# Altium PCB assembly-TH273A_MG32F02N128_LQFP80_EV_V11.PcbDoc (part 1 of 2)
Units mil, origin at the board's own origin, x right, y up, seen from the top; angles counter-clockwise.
Board outline 4724.41 x 2637.8 mil, 2 copper layers (Top Layer, Bottom Layer); 182 components, 166 nets, 741 pads, 331 vias.
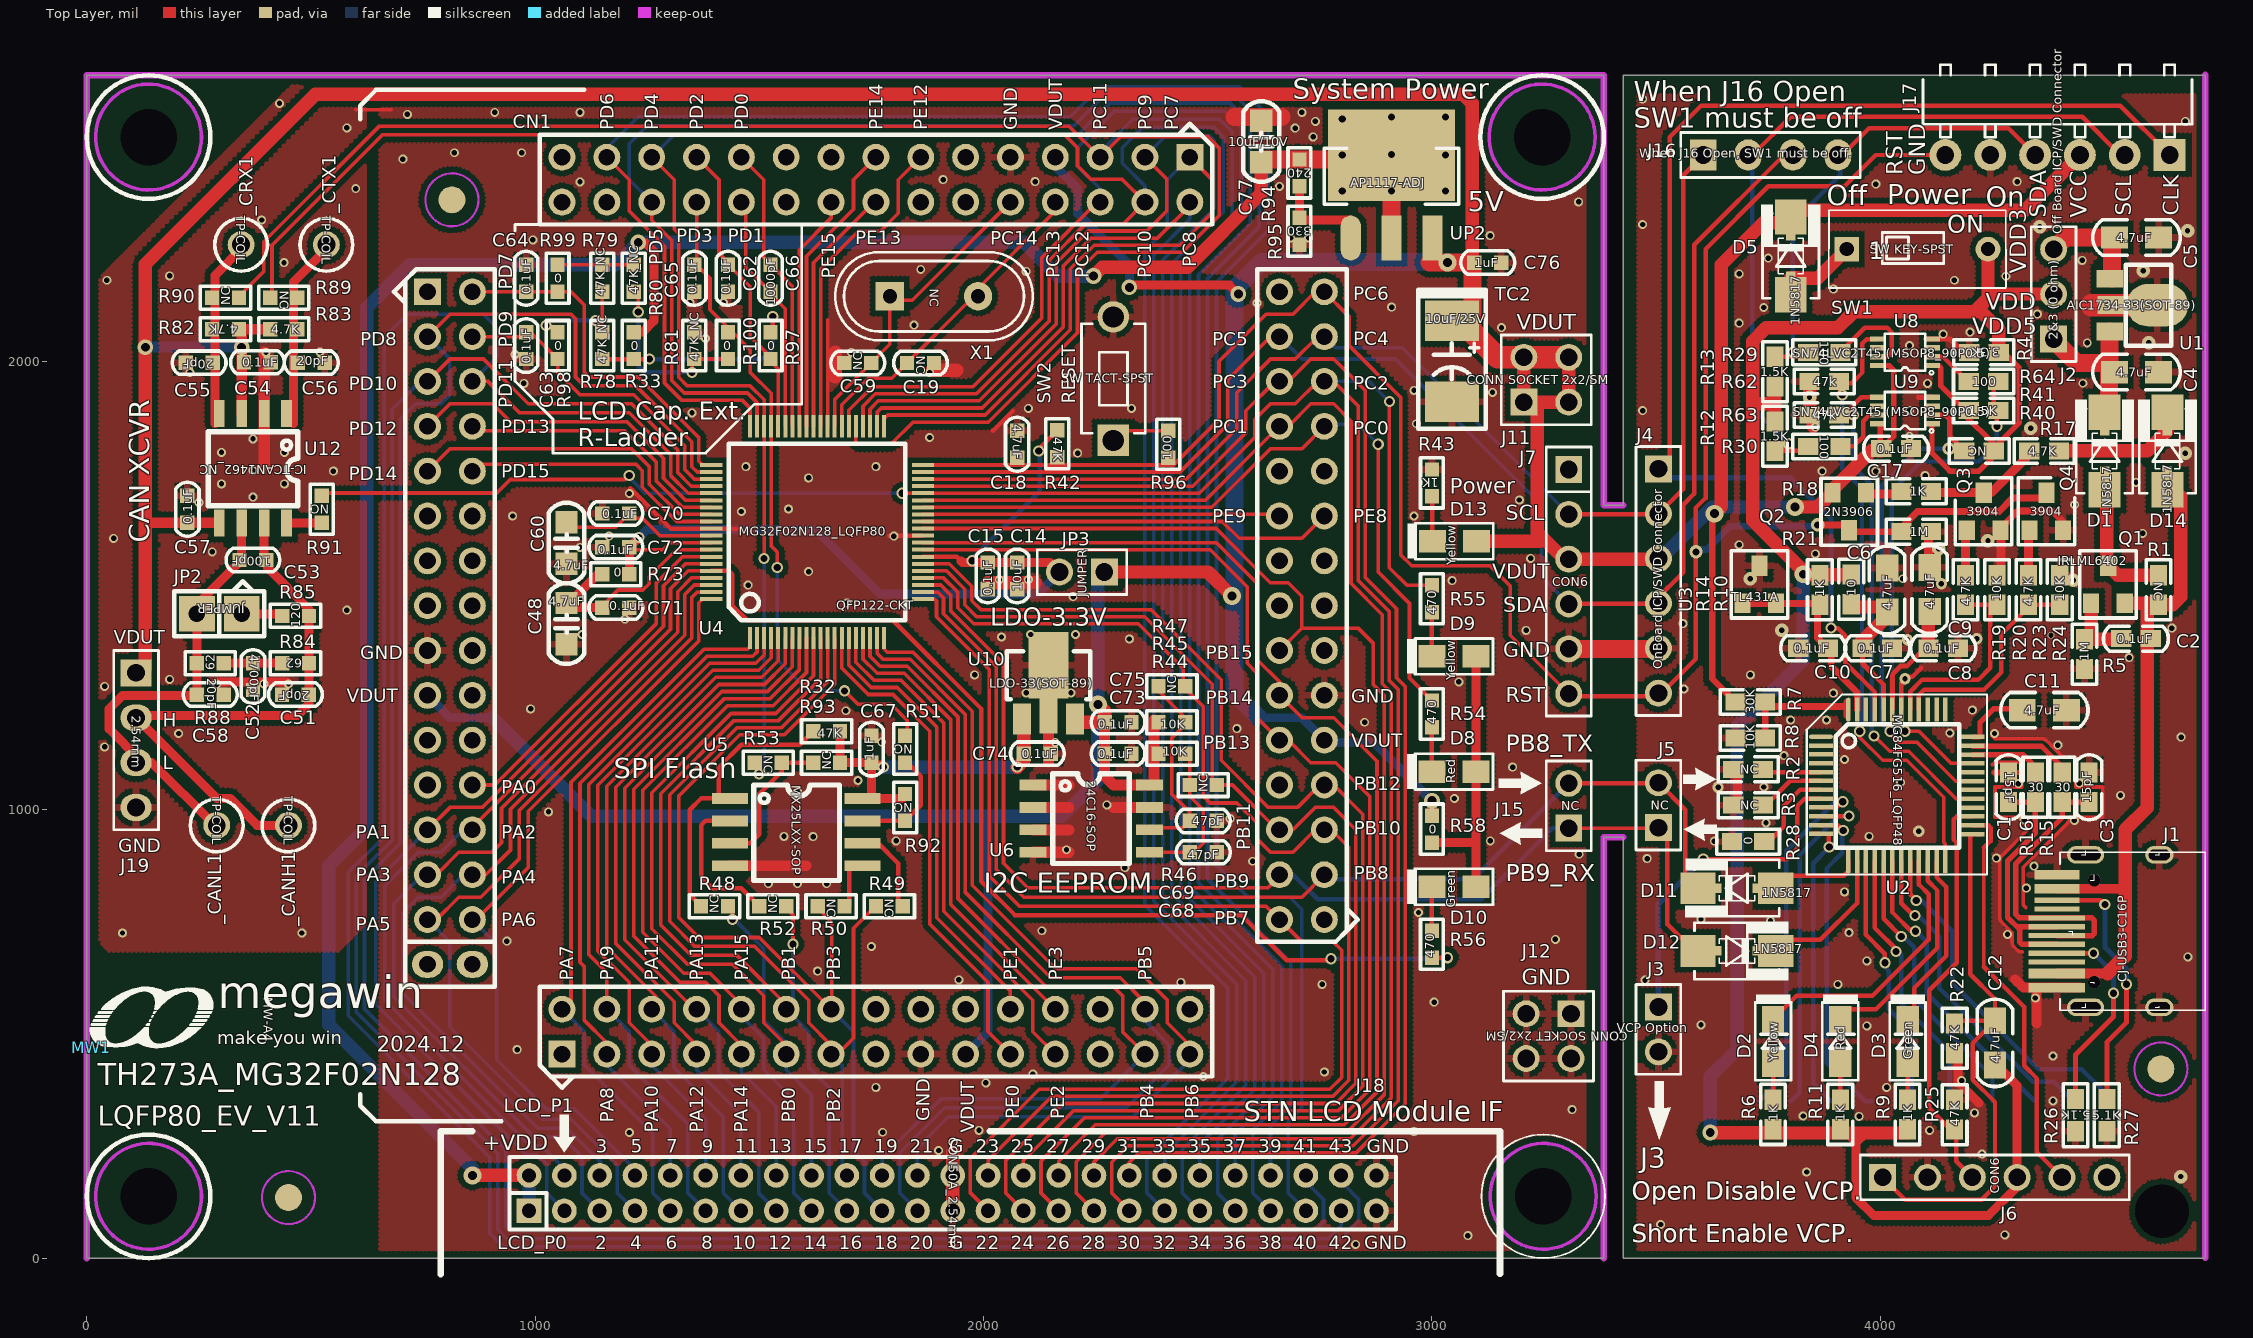
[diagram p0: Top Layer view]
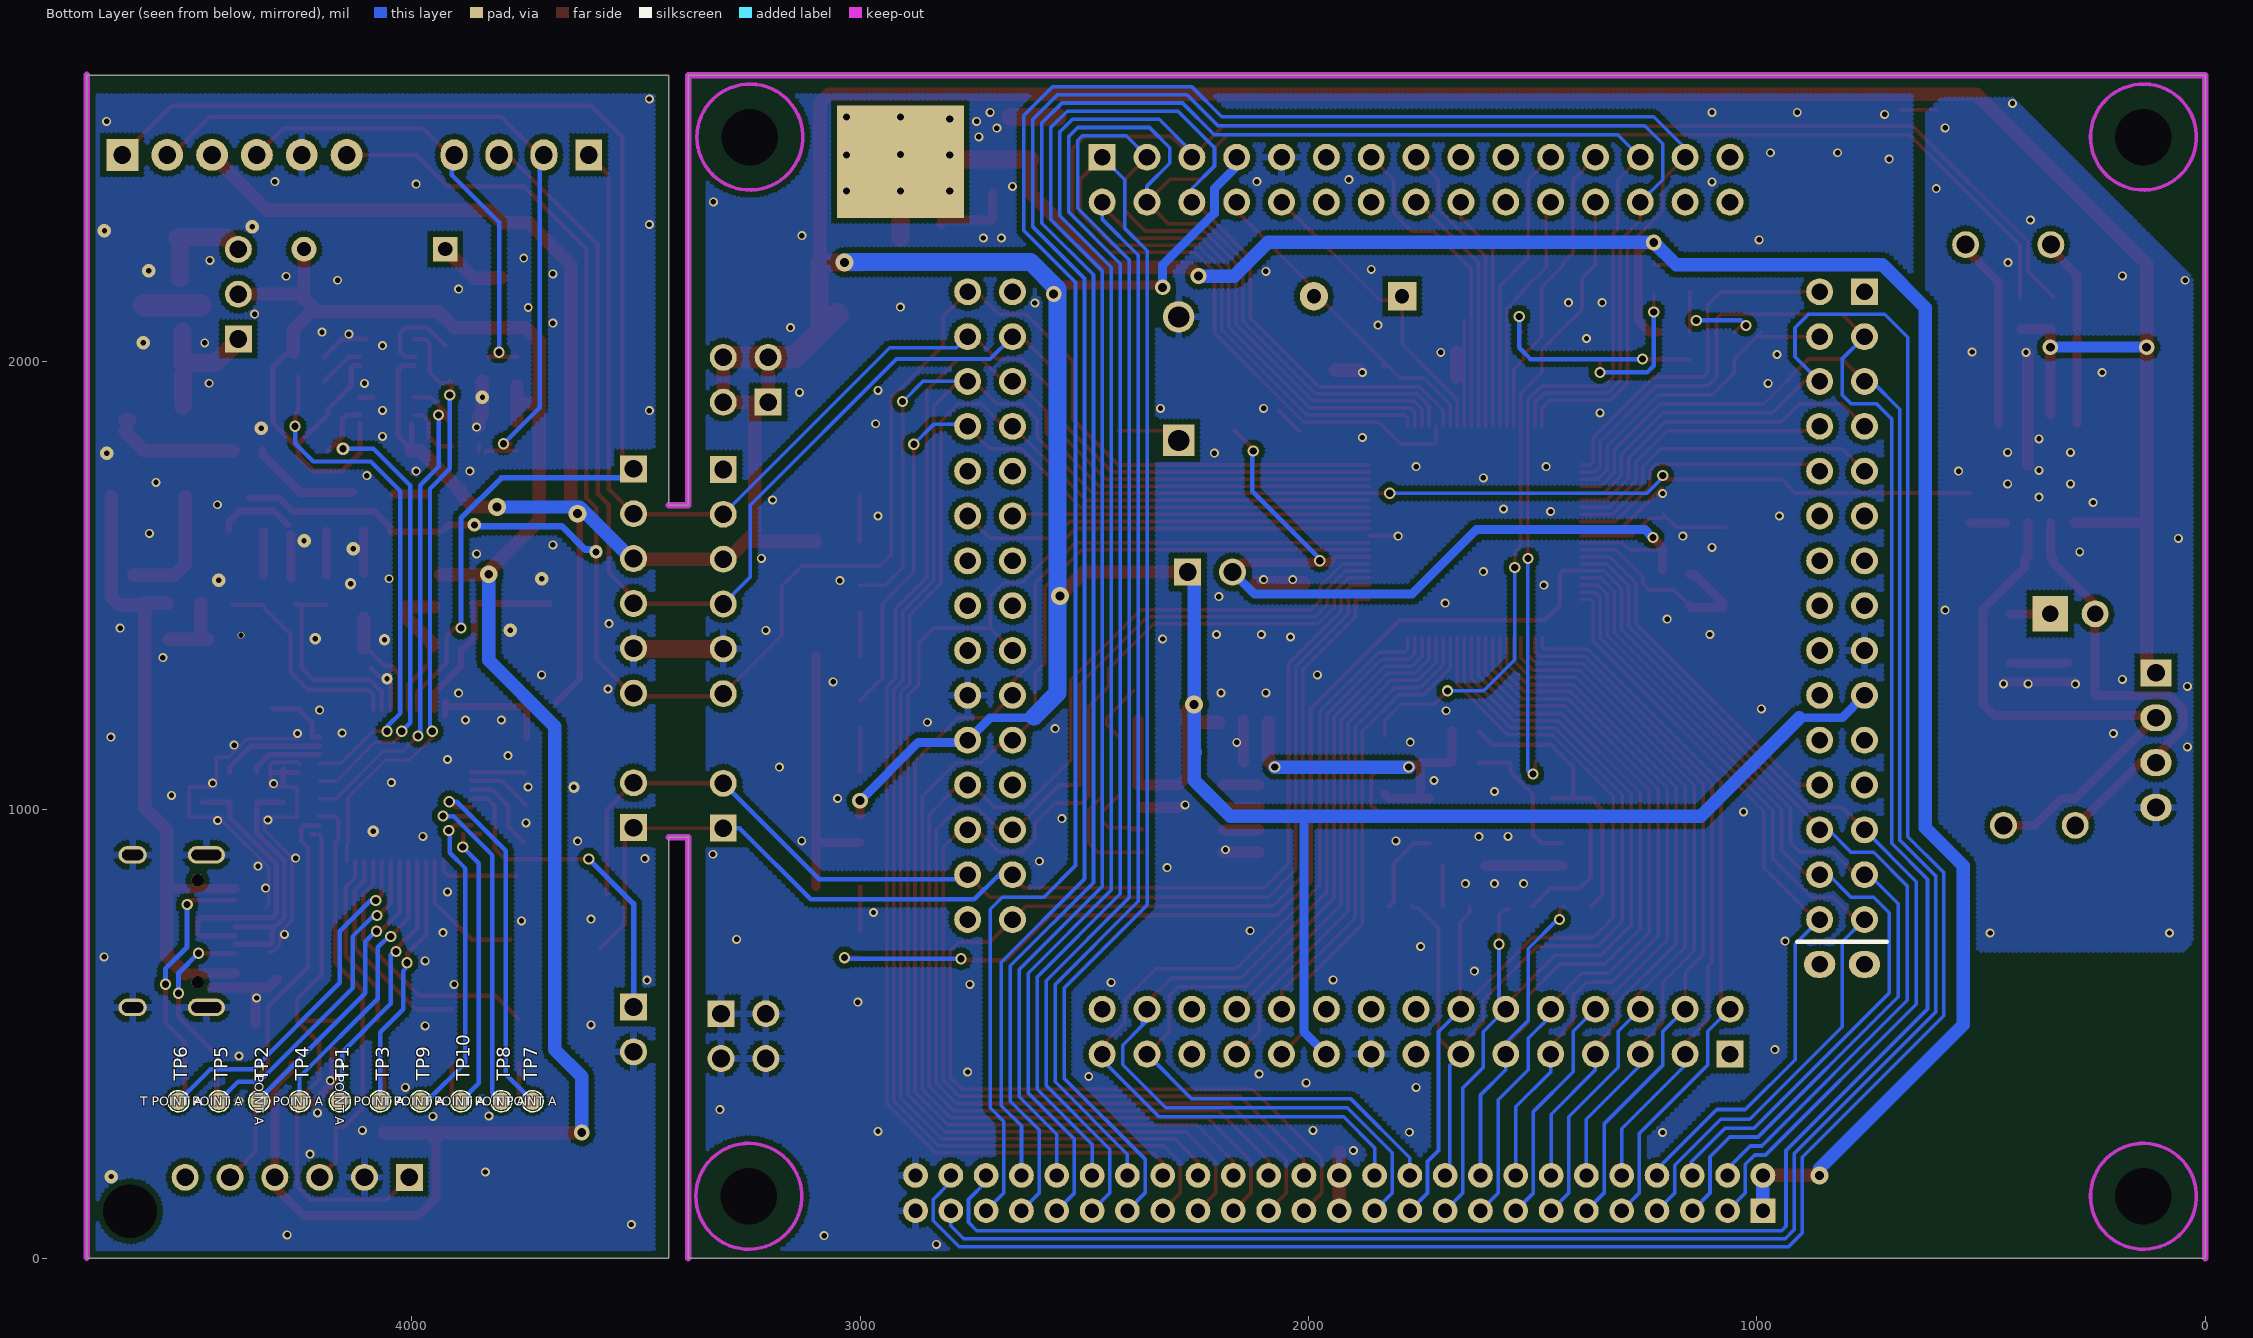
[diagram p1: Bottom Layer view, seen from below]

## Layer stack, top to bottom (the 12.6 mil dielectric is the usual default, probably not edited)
Top Layer: signal copper 1.4
Dielectric: dielectric 12.6, FR-4, Dk 4.8
Bottom Layer: signal copper 1.4

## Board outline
0,0 0,2637.8 3383.31,2637.8 3383.31,1678.74 3426.61,1678.74 3426.61,2637.8 4724.41,2637.8 4724.41,0 3426.61,0 3426.61,938.74 3383.31,938.74 3383.31,0

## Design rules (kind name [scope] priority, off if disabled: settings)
Clearance 12 [All] p1 off: gap=12
Clearance 7 [All] p2 off: gap=7
Clearance 6 [All] p3: gap=6
HoleSize 500-HoleSize [All] p1: absolutevalues=TRUE maxlimit=1500 minlimit=1 maxpercent=80.000 minpercent=20.000
PolygonConnect VIA [ISVIA] p1: connectstyle=Direct reliefconductorwidth=10 reliefentries=4 polygonreliefangle="90 Angle"
PolygonConnect "15 PolygonConnect" [All] p2: connectstyle=Relief reliefconductorwidth=15 reliefentries=4 polygonreliefangle="90 Angle"
RoomDefinition 2_MG32F02N128_LQFP80 [InComponentClass('2_MG32F02N128_LQFP80')] p1: confinementstyle=ConfineIn formatcopy=TRUE lockcomponents=FALSE outline -140.08,-175 4869.96,-175 4869.96,2700 -140.08,2700
RoomDefinition 1_MLink_V14 [InComponentClass('1_MLink_V14')] p2: confinementstyle=ConfineIn formatcopy=TRUE lockcomponents=FALSE outline -75.08,-220 4809.92,-220 4809.92,2810 -75.08,2810
RoutingVias [All] p1: holewidth=16 width=25 viastyle="Through Hole" minholewidth=12 minwidth=25 maxholewidth=28 maxwidth=50
ShortCircuit [All] p1 off: allowed=FALSE
SilkscreenOverComponentPads [All] p1: minsilkscreentomaskgap=10
SolderMaskExpansion [All] p1: expansion=4
UnRoutedNet [All] p1 off:
Width [All] p1: maxlimit=100 minlimit=6 preferedwidth=8
24 further rules are at their usual default settings.

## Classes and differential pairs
component class 1_MLink_V14: C1 C2 C3 C4 C5 C6 C7 C8 C9 C10 C11 C12 C17 D1 D2 D3 D4 D5 D11 D12 D14 J1 J2 J3 J4 J5 J6 J16 J17 MW1 Q1 Q2 Q3 Q4 R1 R2 R3 R4 R5 R6 R7 R8 R9 R10 R11 R12 R13 R14 R15 R16 R17 R18 R19 R20 R21 R22 R23 R24 R25 R26 R27 R28 R29 R30 R40 R41 R62 R63 R64 SW1 TP1 TP2 TP3 TP4 TP5 TP6 TP7 TP8 TP9 TP10 U1 U2 U3 U8 U9
component class 2_MG32F02N128_LQFP80: _CANH1 _CANL1 _CRX1 _CTX1 C14 C15 C18 C19 C48 C51 C52 C53 C54 C55 C56 C57 C58 C59 C60 C62 C63 C64 C65 C66 C67 C68 C69 C70 C71 C72 C73 C74 C75 C76 C77 CN1 D8 D9 D10 D13 J7 J11 J12 J15 J18 J19 JP2 JP3 R32 R33 R42 R43 R44 R45 R46 R47 R48 R49 R50 R51 R52 R53 R54 R55 R56 R58 R73 R78 R79 R80 R81 R82 R83 R84 R85 R88 R89 R90 R91 R92 R93 R94 R95 R96 R97 R98 R99 R100 SW2 TC2 U4 U5 U6 U10 U12 UP2 X1

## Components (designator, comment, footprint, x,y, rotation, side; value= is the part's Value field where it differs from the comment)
_CANH1 "TP-COIL" TPH60-COIL 449.92,965 r0 top
_CANL1 "TP-COIL" TPH60-COIL 289.92,965 r0 top
_CRX1 "TP-COIL" TPH60-COIL 344.41,2260 r0 top
_CTX1 "TP-COIL" TPH60-COIL 534.41,2260 r0 top
C1 "15pF" 0603C 4285.51,1050 r270 top
C2 "0.1uF" 0603C 4569.92,1381.26 r0 top
C3 "15pF" 0603C 4465.51,1050 r270 top
C4 "4.7uF" 0805C 4571.3,1975.94 r0 top
C5 "4.7uF" 0805C 4571.3,2275.94 r0 top
C6 "4.7uF" 0805C 4014.92,1490 r90 top
C7 "0.1uF" 0603C 3992.92,1360 r0 top
C8 "0.1uF" 0603C 4139.92,1360 r0 top
C9 "4.7uF" 0805C 4109.92,1491.26 r90 top
C10 "0.1uF" 0603C 3849.92,1360 r0 top
C11 "4.7uF" 0805C 4365.51,1221.9 r0 top
C12 "4.7uF" 0805C 4255.51,480 r90 top
C14 "10uF" C-0603 2074.88,1521.26 r270 top
C15 "0.1uF" C-0603 2009.37,1521.26 r270 top
C17 "0.1uF" 0603C 4034.92,1805 r180 top
C18 "4.7uF" C-0603 2074.92,1815 r270 top
C19 "NC" C-0603 1859.37,1996.26 r0 top
C48 "4.7uF" C-0805 1069.92,1415 r270 top
C51 "20pF" C-0603 465.43,1256.61 r180 top
C52 "4700pF" C-0603 370.63,1296.81 r270 top
C53 "100pF" C-0603 370.63,1556.81 r180 top
C54 "0.1uF" C-0603 380.63,1997.81 r0 top
C55 "20pF" C-0603 250.63,1996.81 r180 top
C56 "20pF" C-0603 500.63,1996.81 r0 top
C57 "0.1uF" C-0603 224.41,1670 r90 top
C58 "20pF" C-0603 275.43,1256.61 r0 top (schematic designator C30)
C59 "NC" C-0603 1719.37,1996.26 r180 top
C60 "4.7uF" C-0805 1069.92,1594.64 r270 top
C62 "0.1uF" C-0603 1429.92,2185 r270 top
C63 "0.1uF" C-0603 979.92,2035 r270 top
C64 "0.1uF" C-0603 979.92,2185 r90 top
C65 "0.1uF" C-0603 1354.92,2185 r270 top
C66 "1000pF" C-0603 1524.92,2185 r270 top
C67 "1uF" C-0603 1749.92,1135 r90 top
C68 "47pF" C-0603 2489.92,905 r0 top
C69 "47pF" C-0603 2489.92,975 r0 top
C70 "0.1uF" C-0603 1179.92,1660.64 r180 top
C71 "0.1uF" C-0603 1179.92,1450.64 r0 top
C72 "0.1uF" C-0603 1179.92,1585.51 r180 top
C73 "0.1uF" C-0603 2299.92,1125 r0 top
C74 "0.1uF" C-0603 2119.92,1125 r0 top
C75 "0.1uF" C-0603 2299.92,1195 r0 top
C76 "1uF" C-0603 3124.41,2220 r0 top
C77 "10uF/10V" C-0805 2619.37,2490 r90 top
CN1 "QFP122-CKT" QFP122-P2.54-CKT 1759.92,1455 r0 top locked
D1 "1N5817" DIODE_SMA_SOD323 4499.92,1800 r90 top
D2 "Yellow" 0805D 3760.51,483.26 r90 top
D3 "Green" 0805D 4060.51,483.26 r90 top
D4 "Red" 0805D 3910.51,483.26 r90 top
D5 "1N5817" DIODE_SMA_SOD323 3799.92,2235 r90 top
D8 "Red" 0805D 3049.17,1085.04 r180 top
D9 "Yellow" 0805D 3049.17,1341.89 r180 top
D10 "Green" 0805D 3049.17,828.19 r180 top
D11 "1N5817" DIODE_SMA_SOD323 3679.96,825 r180 top
D12 "1N5817" DIODE_SMA_SOD323 3679.96,685 r0 top
D13 "Yellow" 0805D 3049.96,1598.74 r180 top
D14 "1N5817" DIODE_SMA_SOD323 4639.92,1800 r90 top
J1 "CJ-USB3-C16P" USB_CF_16_SMD 4429.2,729.12 r90 top
J2 "2&3 (0 ohm)" PS3P254 4386.34,2049.69 r90 top
J3 "VCP Option" PS2P254 3504.96,560 r270 top
J4 "OnBoard ICP/SWD Connector" PS6P254 3504.96,1760 r270 top
J5 "NC" PS2P254 3504.96,960 r90 top
J6 "CON6" PS6P254 4004.96,180 r0 top
J7 "CON6" PS6P254 3304.96,1758.74 r270 top locked
J11 "CONN SOCKET 2x2/SM" PS2X2P254 3204.96,1908.74 r0 top
J12 "CONN SOCKET 2x2/SM" PS2X2P254 3309.92,545 r180 top
J15 "NC" PS2P254 3304.96,958.74 r90 top
J16 "When J16 Open, SW1 must be off." PS4P254 3604.96,2460 r0 top
J17 "Off Board ICP/SWD Connector" PS6P254_90 4644.96,2460 r180 top
J18 "CON50A_2.54mm" HD25X2-P2.0 986.38,105.63 r0 top locked
J19 "2.54mm" PS4P254 109.92,1305 r270 top
JP2 "JUMPER" SIP2-P2.54-JUMPER 345.63,1436.81 r180 top
JP3 "JUMPER" PS2P254 2269.37,1530 r180 top
MW1 "MW-A4" MEGAWIN_3.4_1 9.96,468.74 r0 top
Q1 "IRLML6402" SOT23 4507.46,1501.97 r0 top
Q2 "2N3906" SOT23 3930.42,1665 r180 top
Q3 "3904" SOT23_132 4229.96,1665 r0 top
Q4 "3904" SOT23_132 4369.96,1665 r0 top
R1 "NC" 0603R#1 4619.96,1490 r270 top
R2 "NC" 0603R#1 3704.96,1090 r0 top
R3 "NC" 0603R#1 3704.96,1010 r0 top
R4 "3.3K" 0603R#1 4230.92,2020 r0 top
R5 "1M" 0603R#1 4454.96,1347 r270 top
R6 "1K" 0603R#1 3760.51,320.26 r270 top
R7 "30K" 0603R#1 3709.92,1240 r180 top
R8 "10K" 0603R#1 3709.92,1160 r0 top
R9 "1K" 0603R#1 4060.51,320.26 r270 top
R10 "10" 0603R#1 3934.92,1491.26 r90 top
R11 "1K" 0603R#1 3910.51,320.26 r270 top
R12 "1.5K" 0603R#1 3764.92,1833 r90 top
R13 "1.5K" 0603R#1 3764.92,1977 r270 top
R14 "1K" 0603R#1 3864.92,1490 r270 top
R15 "30" 0603R#1 4405.51,1050 r90 top
R16 "30" 0603R#1 4345.51,1050 r90 top
R17 "4.7K" 0603R#1 4364.92,1800 r0 top
R18 "1K" 0603R#1 4079.96,1710 r0 top
R19 "4.7K" 0603R#1 4189.96,1490 r270 top
R20 "10K" 0603R#1 4259.96,1490 r270 top
R21 "1M" 0603R#1 4079.96,1620 r180 top
R22 "47K" 0603R#1 4165.51,490 r270 top
R23 "4.7K" 0603R#1 4329.96,1490 r270 top
R24 "10K" 0603R#1 4399.96,1490 r270 top
R25 "47K" 0603R#1 4165.51,320 r270 top
R26 "5.1K" 0603R#2 4434.96,318.74 r270 top
R27 "5.1K" 0603R#2 4504.96,318.74 r90 top
R28 "0" 0603R#2 3704.96,928.74 r180 top
R29 "100" 0603R#2 3874.92,2020 r0 top
R30 "100" 0603R#2 3874.92,1810 r0 top
R32 "47K" R-0603 1649.92,1175 r0 top
R33 "0" R-0603 1219.92,2035 r90 top
R40 "NC" 0603R#1 4219.92,1800 r180 top
R41 "1.5K" 0603R#1 4229.92,1890 r0 top
R42 "47K" R-0603 2164.37,1816.26 r270 top
R43 "1K" R-0603 2999.96,1728.74 r270 top
R44 "10K" R-0603 2419.92,1125 r180 top
R45 "10K" R-0603 2419.92,1195 r180 top
R46 "NC" R-0603 2489.92,1055 r180 top
R47 "NC" R-0603 2419.92,1275 r180 top
R48 "NC" R-0603 1399.92,785 r180 top
R49 "NC" R-0603 1789.92,785 r0 top
R50 "NC" R-0603 1659.92,785 r0 top
R51 "NC" R-0603 1824.92,1135 r270 top
R52 "NC" R-0603 1529.92,785 r180 top
R53 "NC" R-0603 1519.92,1105 r0 top
R54 "470" R-0603 2999.96,1213.47 r270 top
R55 "470" R-0603 2999.96,1470.32 r270 top
R56 "470" R-0603 2999.96,699.76 r90 top
R58 "0" R-0603 2999.96,956.61 r90 top
R62 "47k" 0603R#3 3874.92,1955 r0 top
R63 "47k" 0603R#3 3874.92,1880 r0 top
R64 "100" 0603R#3 4229.92,1955 r180 top
R73 "0" R-0603 1179.92,1525 r0 top
R78 "47K_NC" R-0603 1149.92,2035 r270 top
R79 "47K_NC" R-0603 1149.92,2185 r270 top
R80 "47K_NC" R-0603 1219.92,2185 r90 top
R81 "47K_NC" R-0603 1354.92,2035 r270 top
R82 "4.7K" R-0603 309.37,2071.26 r180 top
R83 "4.7K" R-0603 439.37,2071.26 r0 top
R84 "62" R-0603 465.63,1326.81 r180 top
R85 "120" R-0603 465.63,1432.09 r180 top
R88 "62" R-0603 275.63,1326.81 r180 top
R89 "NC" R-0603 439.37,2141.26 r0 top
R90 "NC" R-0603 309.37,2141.26 r180 top
R91 "NC" R-0603 524.41,1670 r270 top
R92 "NC" R-0603 1824.92,1005 r270 top
R93 "NC" R-0603 1649.92,1105 r180 top
R94 "240" R-0603 2704.41,2420 r270 top
R95 "330" R-0603 2704.41,2290 r270 top
R96 "100" R-0603 2411.92,1815 r90 top
R97 "0" R-0603 1524.92,2035 r90 top
R98 "0" R-0603 1049.92,2035 r90 top
R99 "0" R-0603 1049.92,2185 r90 top
R100 "0" R-0603 1429.92,2035 r270 top
SW1 "SW KEY-SPST" DIP2_SW 3924.96,2250 r0 top
SW2 "SW TACT-SPST" SW_T_2P 2289.37,1961.26 r90 top
TC2 "10uF/25V" C-1812+ 3044.41,2000 r0 top
TP1 "T POINT A" PIN1_1H0 4159.96,350 r90 bottom
TP2 "T POINT A" PIN1_1H0 4339.96,350 r90 bottom
TP3 "T POINT A" PIN1_1H0 4069.96,350 r180 bottom
TP4 "T POINT A" PIN1_1H0 4249.96,350 r180 bottom
TP5 "T POINT A" PIN1_1H0 4429.96,350 r180 bottom
TP6 "T POINT A" PIN1_1H0 4519.96,350 r180 bottom
TP7 "T POINT A" PIN1_1H0 3729.96,350 r180 bottom
TP8 "T POINT A" PIN1_1H0 3799.96,350 r180 bottom
TP9 "T POINT A" PIN1_1H0 3979.96,350 r180 bottom
TP10 "T POINT A" PIN1_1H0 3889.96,350 r90 bottom
U1 "AIC1734-33(SOT-89)" SOT89#1 4511.3,2125 r270 top
U2 "MG84FG516_LQFP48" LQFP48_7X7_050 4036.43,1054.39 r270 top
U3 "TL431A" SOT23 3729.92,1501.97 r0 top
U4 "MG32F02N128_LQFP80" QFP80-P0.4-Z12X12 1628.66,1619.13 r0 top locked
U5 "MX25LXX-SOP" SOP8-P1.27-W6.2+8.1 1434.65,1025 r270 top
U6 "24C16-SOP" SOP8-P1.27-W6.604 2109.92,1055 r270 top
U8 "SN74LVC2T45 (MSOP8_90P0.5)" MSOP8_90P0.5 4054.92,2020 r90 top
U9 "SN74LVC2T45 (MSOP8_90P0.5)" MSOP8_90P0.5 4054.92,1890 r90 top
U10 "LDO-33(SOT-89)" SOT89#2 2144.88,1207 r0 top
U12 "IC-TCAN1462_NC" SOP8-P1.27-W6.2 445.63,1883.09 r180 top
UP2 "AP1117-ADJ" SOT223H\3P 2909.92,2403 r0 top
X1 "NC" X49U 1889.37,2145 r0 top

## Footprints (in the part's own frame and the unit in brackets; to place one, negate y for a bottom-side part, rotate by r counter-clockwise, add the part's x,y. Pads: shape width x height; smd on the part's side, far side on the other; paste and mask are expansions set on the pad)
0603C [mil]
  rect 45x38 smd: 1(33,0) 2(-33,0)
  silkscreen extent -72,-28 72,28
0603R#1 [mil]
  rect 45x38 smd: 1(33,0) 2(-33,0)
  silkscreen extent -67,-28 67,28
0603R#2 [mil]
  rect 45x38 smd: 1(-36,0) 2(36,0)
  silkscreen extent -70,-28 70,28
0603R#3 [mil]
  rect 45x38 smd: 1(-33,0) 2(33,0)
  silkscreen extent -67,-28 67,28
0805C [mil]
  rect 60x50 smd: 1(-49.21,0) 2(49.21,0)
  silkscreen extent -97,-39 97,39
0805D [mil]
  rect 60x50 smd: 1(-49.21,0) 2(49.21,0)
  silkscreen extent -87,-40 104,40
C-0603 [mil]
  rect 32x32 smd: 1(-30,0) 2(30,0)
  silkscreen extent -60,-26 60,26
C-0805 [mil]
  rect 50x50 smd: 1(-46,0) 2(46,0)
  silkscreen extent -90,-40 90,40
C-1812+ [mil]
  rect 120x90 smd: 1(0,90) 2(0,-90)
  silkscreen extent -75,-150 75,160
DIODE_SMA_SOD323 [mm]
  rect 2x1.8 smd: 1(-2.2,0) 2(2.2,0)
  rect 0.95x0.54 smd: 1(-1.35,0) 2(1.35,0)
  silkscreen extent -2.4,-1.68 2.92,1.68
DIP2_SW [mm]
  rect 1.4x1.4 hole 0.8: 1(0,0)
  round 1.4 hole 0.8: 2(8,0)
  silkscreen extent -1.02,-2.2 9.02,2.2
HD25X2-P2.0 [mil]
  rect 55x55 hole 31.5: 1(0,0)
  round 55 hole 31.5: 2(0,78.74) 3(78.74,0) 4(78.74,78.74) 5(157.48,0) 6(157.48,78.74) 7(236.22,0) 8(236.22,78.74) 9(314.96,0) 10(314.96,78.74) 11(393.7,0) 12(393.7,78.74) 13(472.44,0) 14(472.44,78.74) 15(551.18,0) 16(551.18,78.74) 17(629.92,0) 18(629.92,78.74) 19(708.66,0) 20(708.66,78.74) 21(787.4,0) 22(787.4,78.74) 23(866.14,0) 24(866.14,78.74) 25(944.88,0) 26(944.88,78.74) 27(1023.62,0) 28(1023.62,78.74) 29(1102.36,0) 30(1102.36,78.74) 31(1181.1,0) 32(1181.1,78.74) 33(1259.84,0) 34(1259.84,78.74) 35(1338.58,0) 36(1338.58,78.74) 37(1417.32,0) 38(1417.32,78.74) 39(1496.06,0) 40(1496.06,78.74) 41(1574.8,0) 42(1574.8,78.74) 43(1653.54,0) 44(1653.54,78.74) 45(1732.28,0) 46(1732.28,78.74) 47(1811.02,0) 48(1811.02,78.74) 49(1889.76,0) 50(1889.76,78.74)
  silkscreen extent -43,-41 1933,120
LQFP48_7X7_050 [mm]
  oval 0.254x1.35 smd: 1(-2.75,-4.292)
  rect 0.254x1.35 smd: 2(-2.25,-4.292) 3(-1.75,-4.292) 4(-1.25,-4.292) 5(-0.75,-4.292) 6(-0.25,-4.292) 7(0.25,-4.292) 8(0.75,-4.292) 9(1.25,-4.292) 10(1.75,-4.292) 11(2.25,-4.292) 12(2.75,-4.292) 25(2.763,4.292) 26(2.263,4.292) 27(1.763,4.292) 28(1.263,4.292) 29(0.763,4.292) 30(0.263,4.292) 31(-0.237,4.292) 32(-0.737,4.292) 33(-1.237,4.292) 34(-1.737,4.292) 35(-2.237,4.292) 36(-2.737,4.292)
  rect 1.35x0.254 smd: 13(4.286,-2.744) 14(4.286,-2.244) 15(4.286,-1.744) 16(4.286,-1.244) 17(4.286,-0.744) 18(4.286,-0.244) 19(4.286,0.256) 20(4.286,0.756) 21(4.286,1.256) 22(4.286,1.756) 23(4.286,2.256) 24(4.286,2.756) 37(-4.286,2.756) 38(-4.286,2.256) 39(-4.286,1.756) 40(-4.286,1.256) 41(-4.286,0.756) 42(-4.286,0.256) 43(-4.286,-0.244) 44(-4.286,-0.744) 45(-4.286,-1.244) 46(-4.286,-1.744) 47(-4.286,-2.244)
  oval 1.35x0.254 smd: 48(-4.286,-2.744)
  silkscreen extent -5.15,-5.09 5.05,5.11
MEGAWIN_3.4_1 [mil]
  silkscreen extent -2,0 272,135
MSOP8_90P0.5 [mm]
  rect 0.3x0.85 smd: 1(-0.75,-1.55) 2(-0.25,-1.55) 3(0.25,-1.55) 4(0.75,-1.55) 5(0.75,1.55) 6(0.25,1.55) 7(-0.25,1.55) 8(-0.75,1.55)
  silkscreen extent -1.26,-1.61 1.05,1.14
PIN1_1H0 [mm]
  round 1 smd: 1(0,0)
  silkscreen extent -0.6,-0.6 0.6,0.6
PS2P254 [mil]
  rect 60x60 hole 39.37: 1(0,0)
  round 60 hole 39.37: 2(100,0)
  silkscreen extent -50,-50 150,50
PS2X2P254 [mil]
  rect 60x60 hole 39.37: 1(0,0)
  round 60 hole 39.37: 2(0,100) 3(100,0) 4(100,100)
  silkscreen extent -50,-50 150,150
PS3P254 [mil]
  rect 60x60 hole 39.37: 1(0,0)
  round 60 hole 39.37: 2(100,0) 3(200,0)
  silkscreen extent -50,-50 250,50
PS4P254 [mil]
  rect 60x70 hole 39.37: 1(0,0)
  oval 60x70 hole 39.37: 2(100,0) 3(200,0) 4(300,0)
  silkscreen extent -50,-50 350,50
PS6P254 [mil]
  rect 60x60 hole 39.37: 1(0,0)
  round 60 hole 39.37: 2(100,0) 3(200,0) 4(300,0) 5(400,0) 6(500,0)
  silkscreen extent -50,-50 550,50
PS6P254_90 [mm]
  rect 1.8x1.8 hole 1: 1(0,0)
  round 1.8 hole 1: 2(2.54,0) 3(5.08,0) 4(7.62,0) 5(10.16,0) 6(12.7,0)
  silkscreen extent -1.27,-5.11 13.97,-1
QFP80-P0.4-Z12X12 [mm]
  rect 0.229x1.27 smd: 1(-3.8,-6) 2(-3.4,-6) 3(-3,-6) 4(-2.6,-6) 5(-2.2,-6) 6(-1.8,-6) 7(-1.4,-6) 8(-1,-6) 9(-0.6,-6) 10(-0.2,-6) 11(0.2,-6) 12(0.6,-6) 13(1,-6) 14(1.4,-6) 15(1.8,-6) 16(2.2,-6) 17(2.6,-6) 18(3,-6) 19(3.4,-6) 20(3.8,-6) 41(3.8,6) 42(3.4,6) 43(3,6) 44(2.6,6) 45(2.2,6) 46(1.8,6) 47(1.4,6) 48(1,6) 49(0.6,6) 50(0.2,6) 51(-0.2,6) 52(-0.6,6) 53(-1,6) 54(-1.4,6) 55(-1.8,6) 56(-2.2,6) 57(-2.6,6) 58(-3,6) 59(-3.4,6) 60(-3.8,6)
  rect 1.27x0.229 smd: 21(6,-3.8) 22(6,-3.4) 23(6,-3) 24(6,-2.6) 25(6,-2.2) 26(6,-1.8) 27(6,-1.4) 28(6,-1) 29(6,-0.6) 30(6,-0.2) 31(6,0.2) 32(6,0.6) 33(6,1) 34(6,1.4) 35(6,1.8) 36(6,2.2) 37(6,2.6) 38(6,3) 39(6,3.4) 40(6,3.8) 61(-6,3.8) 62(-6,3.4) 63(-6,3) 64(-6,2.6) 65(-6,2.2) 66(-6,1.8) 67(-6,1.4) 68(-6,1) 69(-6,0.6) 70(-6,0.2) 71(-6,-0.2) 72(-6,-0.6) 73(-6,-1) 74(-6,-1.4) 75(-6,-1.8) 76(-6,-2.2) 77(-6,-2.6) 78(-6,-3) 79(-6,-3.4) 80(-6,-3.8)
  silkscreen extent -5,-5 5,5
QFP122-P2.54-CKT [mil]
  rect 60x60 hole 37: 1(-700,-1000) 61(700,1000) 91(-1000,700)
  round 60 hole 37: 2(-700,-900) 3(-600,-1000) 4(-600,-900) 5(-500,-1000) 6(-500,-900) 7(-400,-1000) 8(-400,-900) 9(-300,-1000) 10(-300,-900) 11(-200,-1000) 12(-200,-900) 13(-100,-1000) 14(-100,-900) 15(0,-1000) 16(0,-900) 17(100,-1000) 18(100,-900) 19(200,-1000) 20(200,-900) 21(300,-1000) 22(300,-900) 23(400,-1000) 24(400,-900) 25(500,-1000) 26(500,-900) 27(600,-1000) 28(600,-900) 29(700,-1000) 30(700,-900) 31(1000,-700) 32(900,-700) 33(1000,-600) 34(900,-600) 35(1000,-500) 36(900,-500) 37(1000,-400) 38(900,-400) 39(1000,-300) 40(900,-300) 41(1000,-200) 42(900,-200) 43(1000,-100) 44(900,-100) 45(1000,0) 46(900,0) 47(1000,100) 48(900,100) 49(1000,200) 50(900,200) 51(1000,300) 52(900,300) 53(1000,400) 54(900,400) 55(1000,500) 56(900,500) 57(1000,600) 58(900,600) 59(1000,700) 60(900,700) 62(700,900) 63(600,1000) 64(600,900) 65(500,1000) 66(500,900) 67(400,1000) 68(400,900) 69(300,1000) 70(300,900) 71(200,1000) 72(200,900) 73(100,1000) 74(100,900) 75(0,1000) 76(0,900) 77(-100,1000) 78(-100,900) 79(-200,1000) 80(-200,900) 81(-300,1000) 82(-300,900) 83(-400,1000) 84(-400,900) 85(-500,1000) 86(-500,900) 87(-600,1000) 88(-600,900) 89(-700,1000) 90(-700,900) 92(-900,700) 93(-1000,600) 94(-900,600) 95(-1000,500) 96(-900,500) 97(-1000,400) 98(-900,400) 99(-1000,300) 100(-900,300) 101(-1000,200) 102(-900,200) 103(-1000,100) 104(-900,100) 105(-1000,0) 106(-900,0) 107(-1000,-100) 108(-900,-100) 109(-1000,-200) 110(-900,-200) 111(-1000,-300) 112(-900,-300) 113(-1000,-400) 114(-900,-400) 115(-1000,-500) 116(-900,-500) 117(-1000,-600) 118(-900,-600) 119(-1000,-700) 120(-900,-700)
  oval 70x60 hole 37: 121(-1000,-800) 122(-900,-800)
  silkscreen extent -1150,-1150 1075,1150
R-0603 [mil]
  rect 32x32 smd: 1(-30,0) 2(30,0)
  silkscreen extent -56,-26 56,26
SIP2-P2.54-JUMPER [mil]
  rect 80x80 hole 37: 1(0,0)
  rect 80x80 / inner round 60 / far side round 60 hole 37: 2(100,0)
  silkscreen extent -50,-72 150,50
SOP8-P1.27-W6.2 [mil]
  rect 24x60 smd: 1(0,0) 2(50,0) 3(100,0) 4(150,0) 5(150,244) 6(100,244) 7(50,244) 8(0,244)
  silkscreen extent -25,40 175,205
SOP8-P1.27-W6.2+8.1 [mil]
  rect 24x80 smd: 1(0,0) 2(50,0) 3(100,0) 4(150,0) 5(150,295.28) 6(100,295.28) 7(50,295.28) 8(0,295.28)
  silkscreen extent -30,53 183,244
SOP8-P1.27-W6.604 [mil]
  rect 24x60 smd: 1(0,0) 2(50,0) 3(100,0) 4(150,0) 5(150,260) 6(100,260) 7(50,260) 8(0,260)
  silkscreen extent -25,44 175,215
SOT23 [mil]
  rect 36x43.31 smd: 1(-37.5,-41.97) 2(37.5,-41.97)
  rect 36x46.06 smd: 3(0.5,41.97)
  silkscreen extent -63,-74 63,75
SOT23_132 [mil]
  rect 36x43.31 smd: 1(-37.5,-41.97) 3(37.5,-41.97)
  rect 36x46.06 smd: 2(0.5,41.97)
  silkscreen extent -63,-74 63,75
SOT89#1 [mm]
  rect 1.016x1.5 smd: 1(-1.5,0) 3(1.5,0)
  oval 2.4x3.5 smd: 2(0,2.7)
  rect 1.016x2.6 smd: 2(0,0.6)
  silkscreen extent -2.3,0.9 2.3,3.5
SOT89#2 [mm]
  rect 1.016x1.754 smd: 1(-1.5,-0.127) 3(1.5,-0.127)
  rect 1.016x2.6 smd: 2(0,0.346)
  rect 2.286x3.754 smd: 2(0,2.921)
  silkscreen extent -2.36,1 2.36,3.72
SOT223H\3P [mil]
  oval 45x100 smd: 1(-91,-128)
  rect 45x100 smd: 2(0,-128) 3(91,-128)
  rect 283x250 smd far side: 4(0,42)
  rect 283x204 smd: 4(0,56)
  silkscreen extent -150,-53 150,72
SW_T_2P [mil]
  rect 70x70 hole 47.24: 1(-137.79,0)
  round 70 hole 47.24: 2(137.79,0)
  silkscreen extent -122,-71 122,71
TPH60-COIL [mil]
  round 60 hole 40: 1(0,0)
  silkscreen extent -59,-59 59,59
USB_CF_16_SMD [mm]
  rect 0.55x3.2 smd: A1(-3.2,0.9) A4(-2.4,0.9)
  rect 0.3x3.2 smd: A5(-1.25,0.9) A6(-0.25,0.9) A7(0.25,0.9) B6(0.75,0.9) B7(-0.75,0.9) B8(-1.75,0.9)
  rect 0.3x2.54 smd: A8(1.25,0.9) B5(1.75,0.9)
  rect 0.55x2.54 smd: A9(2.4,0.9) A12(3.2,0.9)
  oval 1x2.1 hole 0.6 slot 1.7 at 90 deg: M1(-4.32,-0.718) M2(4.32,-0.718)
  oval 1x1.6 hole 0.6 slot 1.2 at 90 deg: M3(4.32,-4.898) M4(-4.32,-4.898)
  round 0.7 hole 0.7 unplated: M5(-2.89,-1.218) M6(2.89,-1.218)
  silkscreen extent -4.48,-7.5 4.55,0.74
X49U [mm]
  rect 1.6x1.6 hole 0.8: 1(-2.5,0)
  round 1.6 hole 0.8: 2(2.5,0)
  silkscreen extent -5.6,-2.5 5.6,2.5

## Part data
_CANH1 _CANL1 _CRX1 _CTX1: library part TPH60-COIL
C1 C3 C7 C12: library part "CAP NP_Dup1"
C2 C8 C10 C17: library part "CAP NP"
C4 C5 C19 C59: library part "C NP"
C6 C9 C11: library part CAP
C14: library part "CAP NP_Dup1_C14"
C15 C70 C71 C72: library part "CAP NP_Dup1_C15"
C18 C62 C63 C64 C65 C66 C67 C68 C69 C73 C74 C75: library part "CAP NP_Dup1_C18"
C48 C60: library part CAP_C9
C51 C52 C53 C54 C55 C56 C57 C58 C76: library part CAP-NP
C77: library part CAP-POL
CN1: library part QFP122-CKT_CN1
D1 D5 D11 D12 D14: library part "DIODE SCHOTTKY"
D2 D3 D4: library part Led0_0
D8: library part LED_D8
D9: library part LED_D9
D10: library part LED_D10
D13: library part LED_D13
J1: "TPYE-C-9"
J2: library part CON3
J3 J5: library part CON2
J4 J17: library part CON6
J7: library part CON6_Dup1_J7
J11: library part "CONN SOCKET 2x2/SM_J11"
J12: library part "CONN SOCKET 2x2/SM_J12"
J15: library part CON2_J8
J16 J19: library part CON4
J18: library part CON50A
JP3: library part JUMPER_JP3
MW1: library part MW_A4_2
Q1: library part "MOSFET P GSD"
Q2: library part 2N3906_0
Q3 Q4: library part "NPN BCE"
R1 R2 R3 R4 R28: library part R_Dup4
R5 R6 R7 R8 R9 R11 R12 R13 R17 R18 R19 R22 R23 R25 R26 R27 R29 R30 R82 R83 R84 R85 R88 R94 R95: library part R_Dup2
R10 R14 R15 R16: library part R_Dup5
R20 R21 R24 R32 R33 R44 R45 R46 R47 R48 R49 R50 R51 R52 R53 R73 R78 R79 R80 R81 R89 R90 R91 R92 R93: library part R_Dup1
R40 R41 R62 R63: library part R_Dup3
R42 R96: library part R_Dup3_R42
R43: library part R_Dup4_R43
R54 R97 R98 R99 R100: library part R_Dup4_R54
R55: library part R_Dup4_R55
R56: library part R_Dup4_R56
R58: library part R_Dup4_R58
R64: library part R
SW2: library part "SW TACT-SPST_SW2"
TC2: library part CAP-EC
U1 U10: library part AIC1722-33
U3: library part TL431/CYL
U4: library part IC-MG32F02K128-LQFP80
U5: library part ICM-25LXX
U6: library part ICM-24CXX
U8 U9: library part SN74LVC2T45
U12: library part IC-TCAN1462
UP2: library part ICP-AP1117
X1: library part CRYSTAL

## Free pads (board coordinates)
  round 120 hole 125.98 unplated: 0(137.8,137.8) 0(137.8,2500) 0(3245.51,2500) 0(3248.03,137.8)
  round 60 smd mask+39.37: 0(449.92,135) 0(814.41,2360) 0(4625.51,421.9)
  round 100 hole 120 unplated: 0(4627.72,104.65)

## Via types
v1: diameter 20, hole 12, Top Layer to Bottom Layer, tented both sides, 236 vias
v2: diameter 25, hole 16, Top Layer to Bottom Layer, tented both sides, 57 vias
v3: diameter 30, hole 12, Top Layer to Bottom Layer, tented both sides, 13 vias
v4: diameter 35, hole 20, Top Layer to Bottom Layer, tented both sides, 8 vias
v5: diameter 40, hole 20, Top Layer to Bottom Layer, tented both sides, 7 vias
v6: diameter 25, hole 12, Top Layer to Bottom Layer, tented both sides, 6 vias
v7: diameter 30, hole 16, Top Layer to Bottom Layer, tented both sides, 2 vias
v8: diameter 28, hole 16, Top Layer to Bottom Layer, tented both sides, 1 vias
v9: diameter 15, hole 12, Top Layer to Bottom Layer, tented both sides, 1 vias

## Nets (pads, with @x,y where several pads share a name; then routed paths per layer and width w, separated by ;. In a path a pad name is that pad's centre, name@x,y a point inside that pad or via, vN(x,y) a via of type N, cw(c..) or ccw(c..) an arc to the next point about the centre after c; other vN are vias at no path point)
2.495V: C10.1 R14.1 U2.47 U3.1 U3.2 | length 442.3
  Top Layer w15: U3.1@3692.42,1460 U3.2@3767.42,1460 R14.1@3864.92,1460 ; R14.1@3859.92,1452 3859.92,1383 C10.1@3882.92,1360 3890.51,1360 3890.51,1319.45 3948.1,1261.86 U2.47@3948.1,1223.13
516P24: TP7.1 U2.9 | length 807.9
  Top Layer w10: U2.9@3867.44,1005.18 3901.4,1005.18 v2@3914.96,1018.74
  Bottom Layer w10: TP7.1@3729.96,350 3789.96,410 3789.96,908.74 3898.96,1017.74 v2(3915.96,1017.74)
516P25: TP8.1 U2.10 | length 765.6
  Top Layer w10: U2.10@3867.44,985.49 v2@3929.96,985.49
  Bottom Layer w10: TP8.1@3799.96,350 3819.96,370 3819.96,898.74 3906.96,985.74 v2(3929.96,985.74)
516P26: TP9.1 U2.11 | length 719.6
  Top Layer w10: U2.11@3867.44,965.81 3904.96,965.81 v2@3914.96,955.81
  Bottom Layer w10: v2@3914.96,953.74 3914.96,903.74 3879.96,868.74 3879.96,435.95 3965.91,350 TP9.1@3979.96,350
  other v2: 3916.96,953.74
516P27: TP10.1 U2.12 | length 651.8
  Top Layer w10: U2.12@3847.07,946.12 U2.12@3867.44,946.12 ; v2@3884.96,911.51 3884.96,916.74 U2.12@3884.96,944.74
  Bottom Layer w10: v2(3885.96,916.74) 3849.96,880.74 3849.96,390 TP10.1@3889.96,350
516P32: TP3.1 U2.15 | length 550.9
  Top Layer w10: U2.15@3967.78,885.65 3967.78,720.92 4009.96,678.74 v2@4009.96,668.74
  Bottom Layer w10: 4014.96,643.74 4018.54,640.16 4018.54,555.16 4069.96,503.74 TP3.1@4069.96,350
  other v2: 4009.96,658.74
516P33: TP1.1 U2.16 | length 664
  Top Layer w10: U2.16@3987.47,885.65 3987.47,736.23 v2@4037.46,686.24 ; v2@4039.46,688.24 v2@4041.96,685.74
  Bottom Layer w10: v2@4034.96,688.74 4037.46,686.24 4046.82,676.88 4046.82,566.88 ; 4046.82,618.74 4046.82,566.88 ; TP1.1@4154.96,350 4154.96,458.74 4046.82,566.88
  other v2: 4034.96,683.74
516P34: TP4.1 U2.17 | length 635.3
  Top Layer w10: U2.17@4007.15,885.65 4007.15,756.55 v2(4046.64,717.06)
  Bottom Layer w10: v2@4050.56,717.8 4075.11,693.26 4075.11,578.59 4249.96,403.74 TP4.1@4249.96,350
516P35: TP2.1 U2.18 | length 668.2
  Top Layer w10: U2.18@4026.84,885.65 4026.84,770.86 4073.46,724.24 v2@4074.96,722.74
  Bottom Layer w10: v2@4079.96,728.74 4103.39,705.31 4103.39,590.31 TP2.1@4341.83,351.87
  other v2: 4077.96,728.74
516P36: TP5.1 U2.19 | length 736.6
  Top Layer w10: U2.19@4046.52,885.65 4046.52,791.18 v2@4075.46,762.24
  Bottom Layer w10: v2(4076.96,763.74) 4084.96,763.74 4131.68,717.02 4131.68,602.02 4339.96,393.74 4386.22,393.74 TP5.1@4429.96,350 TP5.1@4420.51,350
516P37: TP6.1 U2.20 | length 795.9
  Top Layer w10: U2.20@4066.21,885.65 4066.21,811.49 v2(4079.96,797.74)
  Bottom Layer w10: v2(4079.96,797.74) 4090.96,797.74 4159.96,728.74 4159.96,613.74 4352.96,420.74 4449.22,420.74 TP6.1@4519.96,350 TP6.1@4510.51,350
+VDD_LCD: C77.1 J18.1 J18.2 R33.2 R94.1 UP2.2 UP2.4 | length 5261.2
  Top Layer w20: R33.2@1219.92,2065 1239.92,2065 1264.92,2090 1264.92,2245 1244.92,2265 v4(1229.92,2265) ; UP2.4@2879.92,2429 UP2.4@2909.92,2459
  Top Layer w30: v5(859.92,184.37) J18.2@986.38,184.37 ; v4(2244.92,2190) 2264.92,2210 2454.92,2210 2619.37,2374.45 C77.1@2619.37,2429
  Top Layer w40: C77.1@2619.37,2450 R94.1@2699.41,2450 ; R94.1@2704.41,2450 UP2.4@2799.92,2450 ; UP2.4@2799.92,2429 UP2.4@2879.92,2429 ; UP2.2@2909.92,2275 v2(2909.92,2380) UP2.4@2909.92,2459
  Bottom Layer w30: v5(859.92,184.37) 859.92,200 539.37,520.55 539.37,874.96 624.37,959.96 624.37,2119.45 719.92,2215 1179.92,2215 v4(1229.92,2265) 2090.56,2265 2165.56,2190 v4(2244.92,2190) ; J18.1@986.38,105.63 J18.2@986.38,184.37
  other v2: 2799.92,2380 3029.92,2380 2799.92,2460 3029.92,2460 2909.92,2461 2799.92,2540 2909.92,2545 3029.92,2545
CAN_H: _CANH1.1 C51.1 C53.1 J19.2 R84.1 R85.1 U12.7 | length 1237.1
  Top Layer w20: J19.2@109.92,1205 114.92,1210 469.92,1210 495.43,1235.51 C51.1@495.43,1256.61 ; J19.2@119.92,1195 289.92,1025 319.92,1025 379.92,965 _CANH1.1@429.92,965 ; C53.1@395.63,1561.81 U12.7@395.63,1639.09 ; C53.1@400.63,1561.81 403.13,1559.31 403.13,1556.81 403.13,1539.31 495.63,1446.81 R85.1@495.63,1432.09 R85.1@495.63,1426.1 ; C51.1@495.63,1256.61 R84.1@495.63,1326.81 R85.1@495.63,1416.81
CAN_L: _CANL1.1 C53.2 C58.1 J19.3 JP2.2 R88.2 U12.6 | length 1032.2
  Top Layer w20: 109.92,1255 139.92,1255 ; C58.1@243.82,1255 139.92,1255 ; C58.1@245.63,1256.61 R88.2@245.63,1326.81 JP2.2@245.63,1436.81 245.63,1456.81 338.13,1549.31 338.13,1556.81 338.13,1559.31 C53.2@340.63,1561.81 ; _CANL1.1@289.92,965 284.92,965 144.92,1105 124.92,1105 117.42,1112.5 49.92,1180 49.92,1225 79.92,1255 139.92,1255 ; C53.2@345.63,1561.81 U12.6@345.63,1639.09
CAN_RX: _CRX1.1 C55.1 R82.2 R90.2 U12.4 | length 400.2
  Top Layer w20: U12.4@285.63,1861.26 285.63,1883.09 285.63,1996.81 285.63,2051.26 ; R82.2@285.63,2071.26 285.63,2141.26 285.63,2191.22 _CRX1.1@349.41,2255
CAN_STB: R91.2 U12.8 | length 78.8
  Top Layer w20: U12.8@445.63,1639.09 R91.2@524.41,1639.09
CAN_TX: _CTX1.1 C56.1 R83.2 R89.2 U12.1 | length 421.6
  Top Layer w20: 460.63,1861 460.63,1883.09 460.63,1996.81 R83.2@460.63,2066.26 ; R83.2@460.63,2071.26 460.63,2141.26 460.63,2176.22 _CTX1.1@539.41,2255
CHIP_VDD: C14.1 C15.1 C72.1 JP3.2 R42.1 R73.2 U4.27 U4.72 | length 1984.6
  Top Layer w8: C72.1@1209.92,1580 1284.92,1580 1300.43,1595.51 U4.72@1392.44,1595.51
  Top Layer w10: U4.27@1864.88,1564.02 1939.88,1564.02 1949.41,1554.49 ; v2@2118.78,1800 2120.85,1802.07 2164.7,1845.92 2165.04,1846.26 R42.1@2164.37,1846.26
  Top Layer w20: R73.2@1209.92,1535 C72.1@1209.92,1580 ; C72.1@1215.43,1590.51 v2(1231.74,1606.82) ; 1949.41,1554.49 1952.64,1551.26 1974.86,1551.26 C15.1@2009.37,1551.26 C14.1@2074.88,1551.26 2148.11,1551.26 JP3.2@2169.37,1530 JP3.2@2177.76,1538.39
  Bottom Layer w10: v2@1972.36,1557.5 2124.92,1710.06 v2@2124.92,1800
  Bottom Layer w20: v2(1231.74,1606.82) 1249.92,1625 1624.92,1625 1769.28,1480.64 2119.92,1480.64 JP3.2@2169.37,1530
  other v2: 1974.86,1555 2122.92,1800
D+: C3.1 J1.A6 J1.B6 R15.2 | length 648.6
  Top Layer w12: J1.A6@4393.76,719.27 4472.29,719.27 4477.02,724 4477.02,753 4471.37,758.64 J1.B6@4393.76,758.64 4309.87,758.64 4301.51,767 4301.51,878.54 4405.51,982.54 R15.2@4405.51,1017 C3.1@4465.51,1017
D-: C1.1 J1.A7 J1.B7 R16.2 | length 590.1
  Top Layer w12: C1.1@4285.51,1017 R16.2@4345.51,1017 4345.51,948 4283.51,886 4283.51,759.54 4309.67,733.39 ; 4305.51,738.96 4315.92,738.96 ; 4310.51,734.23 4310.51,705.23 4316.15,699.59 J1.B7@4393.76,699.59 ; 4310.86,733.9 4315.92,738.96 ; J1.A7@4393.76,738.96 4315.92,738.96
DET_VDUT: R7.2 R8.1 U2.48 | length 292.1
  Top Layer w15: R8.1@3742.92,1160 R7.2@3742.92,1240 3752.92,1230 3920.9,1230 ; U2.48@3924.96,1210 3924.96,1223.13 U2.48@3924.96,1240
DUT_CLK: J4.1 J17.1 U2.45 | length 2846.5
  Top Layer w10: J4.1@3504.96,1760 3529.96,1785 3529.96,2500.04 3599.92,2570 4534.96,2570 J17.1@4644.96,2460 ; v2(3889.92,1405) 3904.92,1405 3921.92,1388 3921.92,1327.92 3987.47,1262.37 U2.45@3987.47,1223.13
  Bottom Layer w12: J4.1@3504.96,1760 3509.96,1760 3529.96,1740 3799.92,1740 3889.92,1650 v2(3889.92,1405)
DUT_RST: C18.2 CN1.59 J4.6 J7.6 J17.6 Q2.3 Q4.2 R21.1 R42.2 R96.1 U4.40 | length 5050.1
  Top Layer w8: U4.40@1864.88,1768.74 2074.92,1768.74 2164.37,1768.74 2411.92,1768.74 2423.66,1768.74 2425.92,1771 2524.92,1870 2524.92,2000 2629.92,2105 2689.92,2105 2739.92,2155 CN1.59@2759.92,2155 2814.92,2100 2814.92,2035 2929.92,1920 2929.92,1568.78 2954.96,1543.74 3129.41,1543.74 3174.41,1498.74 3174.41,1389.29 J7.6@3304.96,1258.74
  Top Layer w10: J7.6@3304.96,1252.74 3504.96,1252.74 3508.59,1256.37 3588.71,1336.49 v7(3588.71,1575) 3588.71,1673.79 3609.96,1695.04 3609.96,2250.04 3749.92,2390 3919.92,2390 3989.92,2460 J17.6@4144.96,2460
  Top Layer w15: v7(3859.92,1635) 3917.95,1635 Q2.3@3929.92,1623.03 ; Q2.3@3937.95,1620 R21.1@4046.96,1620 4046.96,1629.56 4082.4,1665 4264.92,1665 4294.92,1695 Q4.2@4360.55,1695
  Bottom Layer w15: v7(3588.71,1575) 3588.71,1580 3612.92,1580 3664.92,1632 v7@3859.92,1632
DUT_SCL: J16.2 J17.2 R12.2 R30.1 | length 1704.6
  Top Layer w10: J16.2@3704.96,2460 3714.92,2460 3799.92,2545 4449.92,2545 J17.2@4534.92,2460 ; R12.2@3764.92,1800 3794.92,1800 R30.1@3833.23,1800 ; R12.2@3779.92,1816 3780.42,1815.5 3787.42,1808.5 3794.92,1801 ; R30.1@3834.92,1798.31 R30.1@3834.92,1800 ; R30.1@3849.92,1800 3849.92,1810 R30.1@3849.92,1812.69 ; J17.2@4519.92,2460 J17.2@4534.92,2460 ; J17.2@4539.94,2465.02 J17.2@4544.96,2460 J17.2@4534.92,2460
  Bottom Layer w10: J16.2@3714.22,2450.74 3714.22,1896.7 v2(3794.92,1816)
DUT_SDA: J16.4 J17.4 R13.2 R29.1 | length 1034.3
  Top Layer w10: R13.2@3764.92,2010 3804.92,2010 R29.1@3828.92,2010 ; J16.4@3909.94,2455.02 3974.92,2520 4284.96,2520 J17.4@4344.96,2460
  Bottom Layer w10: v2@3804.92,2015 v2(3804.92,2020) 3804.92,2310 3909.94,2415.02 J16.4@3909.94,2455.02
FAIL: D4.2 U2.22 | length 476
  Top Layer w10: D4.2@3910.51,555 3990.06,555 4127.28,692.22 4127.28,819.59 4105.58,841.28 U2.22@4105.58,885.65
FLASH_CEN: R32.1 R48.2 U5.1 | length 672.1
  Top Layer w10: R48.2@1369.92,785 1344.92,810 1344.92,1000 1369.92,1025 U5.1@1409.92,1025 ; U5.1@1457.8,1025 U5.1@1434.65,1025 U5.1@1409.92,1025 ; 1559.92,1145 1549.92,1145 ; R32.1@1619.92,1174.59 R32.1@1619.92,1175 1589.92,1145 1549.92,1145 ; U5.1@1409.92,1025 1409.92,1095 1459.92,1145 1549.92,1145
FLASH_D0: R50.2 U5.5 | length 90
  Top Layer w10: R50.2@1699.92,785 U5.5@1699.92,875
FLASH_D1: R52.2 U5.2 | length 340.8
  Top Layer w10: U5.2@1434.65,975 1379.92,975 1369.92,965 1369.92,850 1394.92,825 1459.92,825 R52.2@1499.92,785
FLASH_D2: R53.2 R93.2 U5.3 | length 324.3
  Top Layer w10: U5.3@1434.65,925 1479.92,925 1499.92,945 1499.92,1035 1549.92,1085 R53.2@1549.92,1105 R93.2@1619.92,1105
FLASH_D3: R51.2 R92.2 U5.7 | length 251.9
  Top Layer w10: U5.7@1729.92,975 R92.2@1824.92,975 1859.92,1010 1859.92,1075 R51.2@1829.92,1105
FLASH_SCK: R49.2 U5.6 | length 197.8
  Top Layer w10: U5.6@1729.92,925 1764.92,925 1809.92,880 1809.92,795 R49.2@1819.92,785
GND: C1.2 C3.2 C4.2 C5.2 C6.2 C7.1 C8.1 C9.2 C10.2 C11.2 C14.2 C15.2 C17.2 C18.1 C19.2 C48.2 C51.2 C52.2 C54.2 C55.2 C56.2 C57.2 C58.2 C59.2 C60.2 C62.2 C63.2 C64.2 C65.2 C67.2 C68.2 C69.2 C70.2 C71.2 C72.2 C73.2 C74.2 C75.2 C76.2 C77.2 CN1.17 CN1.41 CN1.69 CN1.107 J1.A1 J1.A12 J1.M1 J1.M2 J1.M3 J1.M4 J3.2 J4.5 J6.2 J7.5 J12.1 J12.2 J12.3 J12.4 J17.5 J18.25 J18.26 J18.49 J18.50 J19.4 Q3.3 Q4.3 R2.2 R3.2 R4.2 R5.1 R8.2 R20.2 R21.2 R22.1 R24.2 R25.2 R26.2 R27.1 R28.2 R43.1 R62.1 R63.1 R81.1 R95.2 SW2.2 TC2.2 U1.2 U2.42 U3.3 U4.30 U4.49 U4.70 U5.4 U6.1 U6.2 U6.3 U6.4 U6.7 U8.4 U9.4 U10.2 U12.2 | length 5300.8
  Top Layer w8: 599.92,2560.64 679.47,2560.64 ; U4.49@1652.28,1855.35 1652.28,1925 ; 1652.28,1932.29 1652.28,1925 ; 1652.28,2092.64 1652.28,1925 ; 4249,1099.79 4255,1105.79 4285.51,1105.79 4310.68,1105.79 4315.51,1100.96 4315.51,1058 4315.51,1050.5 4307.51,1050.5 4255.51,1050.5 4255.51,983.5 4320.51,983.5 4328.51,983.5 4328.51,977 4328.51,955.04 4271.49,898.02 ; v1@4249.51,1164 4255.04,1158.47 4359.04,1158.47 ; 4271.49,747.52 cw(c4283.51,759.54) 4266.51,759.54 ; 4271.51,898 ccw(c4283.53,885.98) 4266.53,885.98 4266.51,759.54 ; 4304.13,687.57 ccw(c4316.15,699.59) 4316.15,682.59 cw(c4316.15,699.59) 4304.12,687.59 4298.51,693.19 ; 4324.51,781.64 4318.51,787.64 4318.51,825 4318.51,871.5 4417.51,970.5 ccw(c4405.51,982.54) 4422.51,982.54 cw(c4405.51,982.54) 4417.53,970.52 ; 4422.51,983.5 4432.51,983.5 4495.51,983.5 4495.51,1050.5 4443.51,1050.5 4435.51,1050.5 4435.51,1059 4435.51,1116.5 4408.05,1116.5 4388.03,1136.52 4371.08,1153.47 ; 4266.51,759.54 ccw(c4283.51,759.54) 4271.51,747.5 4290.26,728.75 4293.51,725.5 4293.51,722 4293.51,705.23 ; 4293.51,705.23 ccw(c4310.51,705.23) 4298.49,693.21 ; 4293.51,705.23 ccw(c4310.51,705.23) 4298.51,693.19 ; 4359.04,1158.47 cw(c4359.04,1141.47) 4371.08,1153.47 ; 4359.04,1158.47 cw(c4359.04,1141.47) 4371.06,1153.49
  Top Layer w10: 1212.17,1717.24 1217.14,1712.27 1302.4,1627.01 U4.70@1392.44,1627.01 1449.41,1627.01 ; 1789.88,1611.26 1799.86,1611.26 U4.30@1864.88,1611.26 ; 2020.92,1845.39 2064.78,1889.24 ; U2.42@4046.52,1223.13 4046.52,1283.6 v6(4054.92,1292) 4058.92,1296 4070.92,1296 4090.92,1316
  Top Layer w12: 4084.92,1919.53 U9.4@4115.94,1919.53 ; U8.4@4100.94,2049.53 U8.4@4115.94,2049.53 4139.92,2049.53 4155.39,2049.53 4191.42,2013.5 R4.2@4194.92,2010 ; 4253.51,1083 C1.2@4285.51,1083 C1.2@4286.51,1083 ; 4286.51,1054 C1.2@4286.51,1083 ; C1.2@4286.51,1091 C1.2@4286.51,1083 ; 4313.51,1083 C1.2@4286.51,1083
  Top Layer w15: Q3.3@4275.21,1635.29 4306.16,1666.24 4383.62,1666.24 4407.46,1642.4 Q4.3@4407.46,1623.03
  Top Layer w20: v1@289.92,1285 370.63,1285 394.92,1285 445.56,1285 v1(449.92,1280.64) ; R3.2@3680.96,1010 3680.96,1090 R2.2@3680.96,1090.09 ; C9.2@4106.96,1528 4106.96,1540.47 4106.96,1582 R21.2@4106.96,1620 ; R22.1@4173.51,461 4173.51,457 4173.51,395.74 4173.51,391.89 4175.31,390.09 4188.96,376.44 4220,345.4 ; R20.2@4268.96,1515 4268.96,1523 Q3.3@4268.96,1612.53
  Top Layer w22: 4300.51,621.9 4319.3,603.12 J1.A1@4393.76,603.12 J1.A1@4445.51,603.12 ; 4348.4,522.79 4348.4,580 J1.A1@4348.4,597.25
  Top Layer w24: U5.4@1434.65,875 1604.41,875 ; 2144.92,1105.88 2144.92,1125 2144.92,1150 U10.2@2144.92,1200.64
  Top Layer w25: 395.63,1767.81 U12.2@395.63,1883.09 395.63,1997.81 v1@395.63,2020 ; U6.4@2109.92,905 2184.92,905 v1@2189.92,905 ; U6.3@2109.92,955 2189.92,955 ; U6.2@2109.92,1005 2189.92,1005 ; U6.1@2109.92,1055 2189.92,1055 ; 2289.92,1005 U6.7@2369.92,1005
  Top Layer w30: 1669.3,1964.96 1669.3,1996.26 1669.3,2019.94 ; v1@1884.98,1980.03 1889.37,1980.03 1939.96,1980.03 ; J18.25@1931.26,105.63 J18.26@1931.26,184.37 1931.26,236.26 ; C15.2@2009.37,1506.26 2034.92,1506.26 2074.88,1506.26 2099.92,1506.26 2114.86,1506.26 ; R63.1@3841.92,1880 v3(3841.92,1920) R62.1@3841.92,1955 ; v1@3849.92,1855 R63.1@3849.92,1875
  Top Layer w40: 2559.92,2545 2619.37,2545 2664.86,2545 ; J7.5@3304.96,1358.74 J4.5@3504.96,1358.74
  Top Layer w50: 4471.74,2125 U1.2@4534.92,2125 U1.2@4596.3,2125
  other v1: 2829.92,30.64 3079.86,50 4277.51,51.9 3509.86,75 3835.51,191.9 4226.51,231.9 1899.86,240 1209.86,280 1774.92,280.64 2959.92,282.8 1989.86,285 4109.86,285 3952.51,316 3827.51,317 4209.86,323.74 3312.38,331.22 4384.92,350.64 1759.92,380.64 4013.96,380.64 2004.92,390.64 4180.96,395.74 2489.86,405 2109.92,410.64 2759.86,415 4384.92,450.64 959.86,465 3969.86,518 3599.86,520 3004.92,570.64 4345.51,580 2754.92,610.64 3904.96,610.64 2439.86,615 3474.96,620 1944.92,620.64 1629.86,640 3969.86,662.74 4685.51,671.9 1749.86,695 936.92,706.9 3274.92,710.64 4283.51,722 79.86,725 479.86,725 3929.86,725.74 2129.86,730 3754.96,751.9 3599.86,756 2969.92,770.64 3919.86,816.74 4325.51,825 1519.86,835 1584.92,835 1649.86,835 2314.92,870.64 4342.51,874 2599.86,885 3479.92,890.64 4258.51,891.9 3327.96,900.64 2184.92,910.64 3629.86,930 1804.92,930.64 3129.92,930.64 1619.86,940 1554.92,940.64 3974.92,940.64 3744.92,970.64 4432.51,976 4320.51,977 2549.86,980 1029.86,995 2274.92,1010.64 3049.86,1025 4535.51,1031.9 1584.92,1040.64 3739.92,1050.64 4307.51,1058 4443.51,1059 4044.92,1060.64 1719.86,1065 3179.86,1095 3919.96,1111.9 3784.92,1120.64 39.86,1140 4395.51,1144 2159.86,1150 1772.92,1150.64 4670.51,1161.9 204.92,1170 4254.51,1170 4154.92,1171 2564.92,1180.64 2849.86,1195 3799.86,1200 3879.86,1200 1692.92,1220.64 4204.96,1221.9 989.86,1225 3894.96,1260 2094.92,1260.64 2194.92,1260.64 3561.92,1269.26 39.86,1275 289.86,1280 394.92,1280.64 3059.86,1285 184.92,1290.64 1979.92,1300.64 3709.92,1300.64 4554.51,1339 2324.92,1380.64 2039.86,1385 1104.92,1390.64 2104.92,1390.64 2204.92,1390.64 3209.86,1400 4649.86,1405 3559.86,1415 1199.86,1425 579.86,1445 1694.92,1460.64 2199.86,1475 1474.92,1500.64 3044.92,1510.64 2034.92,1513 2099.92,1513 4049.86,1515 1609.92,1530.64 3219.92,1560.64 3854.92,1570.64 279.86,1575 1099.92,1585 3684.92,1590.64 59.86,1605 1164.92,1610 1799.86,1610 4584.92,1616.26 949.86,1655 2959.86,1655 1459.86,1665 1564.92,1670.64 4432.95,1680 249.86,1685 3194.92,1690.64 370.63,1696.81 1209.86,1705 300.63,1726.81 440.63,1726.81 4569.86,1730 1609.86,1740 4099.92,1745 549.86,1755 3869.86,1755 3989.92,1755 370.63,1756.81 1469.86,1765 1759.86,1765 2209.86,1795 300.63,1796.81 440.63,1796.81 370.63,1826.81 1879.86,1830 4064.92,1832.56 3854.92,1853 2964.92,1860.64 1349.86,1885 3469.86,1890 4064.92,1890.64 2099.86,1895 2329.86,1895 3134.92,1930.64 2959.92,1935 974.92,1950.64 4104.92,1950.64 4451.3,1950.94 229.86,1975 1879.86,1975 954.92,2015 399.86,2020 1704.92,2020 519.92,2020.64 4064.86,2035 4461.24,2040.94 1379.92,2050.64 4139.92,2060.64 4199.86,2065 3154.92,2075 1844.92,2080.64 3684.92,2085 4349.86,2105 3739.86,2120 2909.92,2120.64 2609.92,2130 1344.92,2130.64 1419.92,2130.64 3894.92,2160.64 44.92,2180.64 4164.92,2180.64 4279.86,2189.59 184.92,2190.64 3684.92,2195 2094.92,2200.64 1859.86,2205 439.86,2220 4449.86,2225 3749.86,2230 994.92,2270.64 2684.92,2275 2724.92,2275 3129.86,2280 3469.86,2305 389.86,2315 3327.17,2355.32 599.86,2385 2659.86,2390 3989.86,2395 1099.86,2400 2114.92,2400.64 4304.92,2400.64 1909.86,2405 704.92,2450.64 819.86,2465 969.86,2465 2734.92,2500.64 2694.92,2520 579.92,2520.64 2739.86,2535 4679.86,2535 714.92,2550.64 909.86,2555 1099.86,2555 2709.92,2555 429.86,2575 3469.86,2585
  other v3: 4669.96,181.9 3779.92,1400 4429.92,1511.26 3709.86,1515 4130.51,1582 4239.86,1600 4679.86,1795 4334.92,1850.64 4598.34,2041.59 4585.89,2201.69 4684.92,2290.64 4354.92,2299.69
  other v6: 4085.51,952 3638.03,1050 4060.51,1379 4214.92,1381.26 4135.92,1504
  other v9: 4380.51,1389
I2C_SCL: C69.1 R45.1 R47.2 U6.6 | length 460.1
  Top Layer w8: U6.6@2369.92,955 U6.6@2394.92,955 ; U6.6@2374.92,960 2444.92,960 C69.1@2459.92,975 2459.92,995 2419.92,1035 2419.92,1160 2449.92,1190 R45.1@2449.92,1195 2449.92,1205 R47.2@2389.92,1265
I2C_SDA: C68.1 R44.1 R46.2 U6.5 | length 330.7
  Top Layer w8: U6.5@2369.92,905 C68.1@2459.92,905 2469.92,905 2489.92,925 2489.92,1000 2459.92,1030 2459.92,1035 R46.2@2459.92,1055 R44.1@2459.92,1115
ICP/SWD_SCL: R40.1 U2.31 U9.2 | length 1093
  Top Layer w8: v2@4021.92,1168 4039.92,1150 4081.92,1150 4168.19,1063.73 U2.31@4205.42,1063.73
  Top Layer w12: U9.2@4115.94,1880.16 4144.76,1880.16 4154.92,1870 4154.92,1832 R40.1@4186.92,1800
  Bottom Layer w10: v2(4021.92,1175) 4002.92,1194 4002.92,1723 4084.92,1805 v8(4152.99,1805)
ICP/SWD_SDA: R41.1 R64.1 U2.33 | length 1167.1
  Top Layer w8: v2(4054.92,1175) 4085.92,1175 4157.82,1103.1 U2.33@4205.42,1103.1
  Top Layer w10: R64.1@4252.92,1965 4252.92,1955 4252.92,1890 4257.92,1885 4259.92,1883 v2(4259.92,1855)
  Bottom Layer w10: 4024.92,1505 4024.92,1495 ; v2@4052.92,1175 4052.92,1187 4024.92,1215 4024.92,1495 ; v2(4259.92,1855) 4259.92,1817 4219.39,1776.47 4091.39,1776.47 4024.92,1710 4024.92,1495
LCD_P0: CN1.115 J18.3 U4.75 | length 2016.9
  Top Layer w8: CN1.115@759.92,955 809.92,1005 882.27,1005 1286.14,1408.88 1286.14,1499.33 1335.08,1548.27 U4.75@1392.44,1548.27
  Bottom Layer w8: CN1.115@759.92,955 644.37,839.45 644.37,566.41 980.78,230 1004.92,230 1025.75,209.17 1025.75,145 J18.3@1065.12,105.63
LCD_P1: CN1.116 J18.4 R56.1 U4.76 | length 4206
  Top Layer w8: CN1.116@859.92,955 859.92,960.38 1301.89,1402.35 1301.89,1492.81 1341.6,1532.52 U4.76@1392.44,1532.52
  Top Layer w10: U4.76@1392.44,1532.52 1432.4,1532.52 1439.92,1525 1439.92,1455 1472.64,1422.28 1797.64,1422.28 1994.37,1225.55 1994.37,840.55 2069.92,765 2574.92,765 2676,663.92 2771.18,663.92 v2(2774.92,667.66) ; R56.1@2999.96,669.76 v2@3034.17,669.76
  Bottom Layer w8: CN1.116@859.92,955 839.92,955 789.92,905 739.41,905 664.37,829.96 664.37,574.69 989.06,250 1014.92,250 1065.12,199.8 J18.4@1065.12,184.37
  Bottom Layer w10: v2(2774.92,667.66) v2@3034.41,667.66
  other v2: 3034.41,670
LCD_P2: CN1.117 J18.5 U4.77 | length 2023.1
  Top Layer w8: CN1.117@779.92,855 829.92,905 903.94,905 924.92,925.98 924.92,1003.11 1317.64,1395.83 1317.64,1486.29 1348.12,1516.77 U4.77@1392.44,1516.77
  Bottom Layer w8: CN1.117@755.9,855 CN1.117@759.92,855 ; CN1.117@779.92,855 CN1.117@759.92,855 ; J18.5@1143.86,105.63 1104.49,145 1104.49,226.14 1060.63,270 997.35,270 684.37,582.98 684.37,789.96 749.41,855 CN1.117@759.92,855
LCD_P3: CN1.118 J18.6 U4.78 | length 1893.8
  Top Layer w8: CN1.118@859.92,855 889.92,855 944.92,910 944.92,1000.84 1333.39,1389.31 1333.39,1479.76 1354.65,1501.02 U4.78@1392.44,1501.02
  Bottom Layer w8: CN1.118@859.92,855 839.92,855 789.92,805 739.41,805 704.37,769.96 704.37,591.26 1005.63,290 1070.63,290 1146.38,214.25 J18.6@1146.38,194.37
LCD_P4: CN1.119 J18.7 U4.79 | length 1930.1
  Top Layer w8: CN1.119@759.92,755 779.92,755 829.92,805 878.94,805 964.92,890.98 964.92,998.57 1349.13,1382.78 1349.13,1473.24 1361.17,1485.28 U4.79@1392.44,1485.28
  Bottom Layer w8: CN1.119@759.92,755 809.37,705.55 809.37,516.26 1015.63,310 1080.63,310 1183.23,207.4 1183.23,145 J18.7@1222.6,105.63
LCD_P5: CN1.120 J18.8 U4.80 | length 1729.8
  Top Layer w8: CN1.120@859.92,755 868.94,755 984.92,870.98 984.92,996.3 1364.88,1376.26 1364.88,1461.26 1373.15,1469.53 U4.80@1392.44,1469.53
  Bottom Layer w8: CN1.120@839.92,755 CN1.120@859.92,755 914.37,700.55 914.37,442.68 1025.63,331.42 1089.21,331.42 1222.6,198.03 J18.8@1222.6,184.37
LCD_P6: CN1.2 J18.9 U4.1 | length 1681.9
  Top Layer w8: CN1.2@1059.92,555 1079.92,575 1079.92,1061.3 1376.62,1358 1473.43,1358 1479.05,1363.62 U4.1@1479.05,1382.91
  Bottom Layer w8: CN1.2@1059.92,555 1109.37,505.55 ; 1109.37,431.26 1109.37,505.55 ; J18.9@1301.34,105.63 1261.97,145 1261.97,277.95 1109.37,430.55 1109.37,505.55
LCD_P7: CN1.3 J18.10 U4.2 | length 1505.4
  Top Layer w8: CN1.3@1159.92,455 1159.92,480 1109.92,530 1109.92,650 1099.92,660 1099.92,1059.03 1383.14,1342.25 1485.41,1342.25 1494.8,1351.64 U4.2@1494.8,1382.91
  Bottom Layer w8: CN1.3@1159.92,455 1159.92,430 1301.34,288.58 J18.10@1301.34,184.37
LCD_P8: CN1.4 J18.11 U4.3 | length 1626.8
  Top Layer w8: CN1.4@1159.92,535 CN1.4@1159.92,555 1159.92,636.72 1119.92,676.72 1119.92,1056.76 1389.67,1326.5 1491.94,1326.5 1510.55,1345.12 U4.3@1510.55,1382.91
  Bottom Layer w8: CN1.4@1159.92,555 1209.37,505.55 1209.37,430.55 1340.71,299.21 1340.71,145 J18.11@1380.08,105.63
LCD_P9: CN1.5 J18.12 U4.4 | length 1518
  Top Layer w8: CN1.5@1259.92,455 1259.92,475 1209.92,525 1209.92,615 1139.92,685 1139.92,1054.49 1396.19,1310.76 1498.46,1310.76 1526.3,1338.6 U4.4@1526.3,1382.91
  Bottom Layer w8: CN1.5@1259.92,455 1259.92,430 1380.08,309.84 J18.12@1380.08,184.37
LCD_P10: CN1.6 J18.13 U4.5 | length 1618.5
  Top Layer w8: CN1.6@1270.18,560 1270.18,583.02 1159.92,693.28 1159.92,1052.22 1402.71,1295.01 1504.98,1295.01 1542.05,1332.07 U4.5@1542.05,1382.91
  Bottom Layer w8: CN1.6@1259.92,555 1309.37,505.55 1309.37,425.55 1419.45,315.47 1419.45,145 J18.13@1458.82,105.63
LCD_P11: CN1.7 J18.14 U4.6 | length 1554.8
  Top Layer w8: CN1.7@1359.92,455 1359.92,475 1309.92,525 1309.92,571.57 1179.92,701.57 1179.92,1049.94 1409.24,1279.26 1511.51,1279.26 1557.8,1325.55 U4.6@1557.8,1382.91
  Bottom Layer w8: CN1.7@1359.92,430.71 CN1.7@1359.92,455 1359.92,420 1458.82,321.1 J18.14@1458.82,184.37
LCD_P12: CN1.8 J18.15 U4.7 | length 1712.6
  Top Layer w8: CN1.8@1357.35,552.43 1199.92,709.85 1199.92,1047.67 1415.76,1263.51 1518.03,1263.51 1573.54,1319.03 U4.7@1573.54,1382.91
  Bottom Layer w8: CN1.8@1359.92,555 1409.37,505.55 ; 1409.37,426.26 1409.37,505.55 ; J18.15@1537.56,105.63 1498.19,145 1498.19,326.73 1409.37,415.55 1409.37,505.55
LCD_P13: CN1.9 J18.16 U4.8 | length 1590.6
  Top Layer w8: CN1.9@1459.92,455 1459.92,475 1409.92,525 1409.92,585 1379.92,615 1323.06,615 1219.92,718.14 1219.92,1045.4 1422.28,1247.76 1524.55,1247.76 1589.29,1312.5 U4.8@1589.29,1382.91
  Bottom Layer w8: CN1.9@1459.92,440.71 CN1.9@1459.92,455 1459.92,415 1537.56,337.36 J18.16@1537.56,184.37
LCD_P14: CN1.10 J18.17 U4.9 | length 1727.4
  Top Layer w8: CN1.10@1459.92,565 1389.92,635 1331.34,635 1239.92,726.42 1239.92,1043.13 1428.81,1232.02 1531.07,1232.02 1605.04,1305.98 U4.9@1605.04,1382.91
  Bottom Layer w8: CN1.10@1459.92,555 1459.92,540 1509.92,490 ; 1509.92,431.26 1509.92,490 ; J18.17@1616.3,105.63 1576.93,145 1576.93,352.99 1509.92,420 1509.92,490
LCD_P15: CN1.11 J18.18 R48.1 U4.10 | length 2010.8
  Top Layer w8: R48.1@1429.92,785 1439.92,775 1439.92,760 v2@1442.39,757.53 ; CN1.11@1559.92,455 1559.92,475 1509.92,525 1509.92,585 1439.92,655 1339.63,655 1259.92,734.71 1259.92,1037.52 1436.9,1214.5 1536.31,1214.5 1620.79,1298.98 U4.10@1620.79,1382.91
  Bottom Layer w8: v2@1442.39,757.53 1509.92,690 1509.92,530 1559.92,480 CN1.11@1559.92,455 ; CN1.11@1559.92,440.71 CN1.11@1559.92,455 ; J18.18@1616.3,184.37 1616.3,363.62 1559.92,420 CN1.11@1559.92,455
  other v2: 1439.86,755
